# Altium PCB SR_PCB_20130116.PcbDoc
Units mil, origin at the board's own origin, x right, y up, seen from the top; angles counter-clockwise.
Board outline 7185 x 3715 mil, 2 copper layers (Top Layer, Bottom Layer); 142 components, 94 nets, 383 pads, 150 vias.
Unrouted connection lines stored in the file: 1.
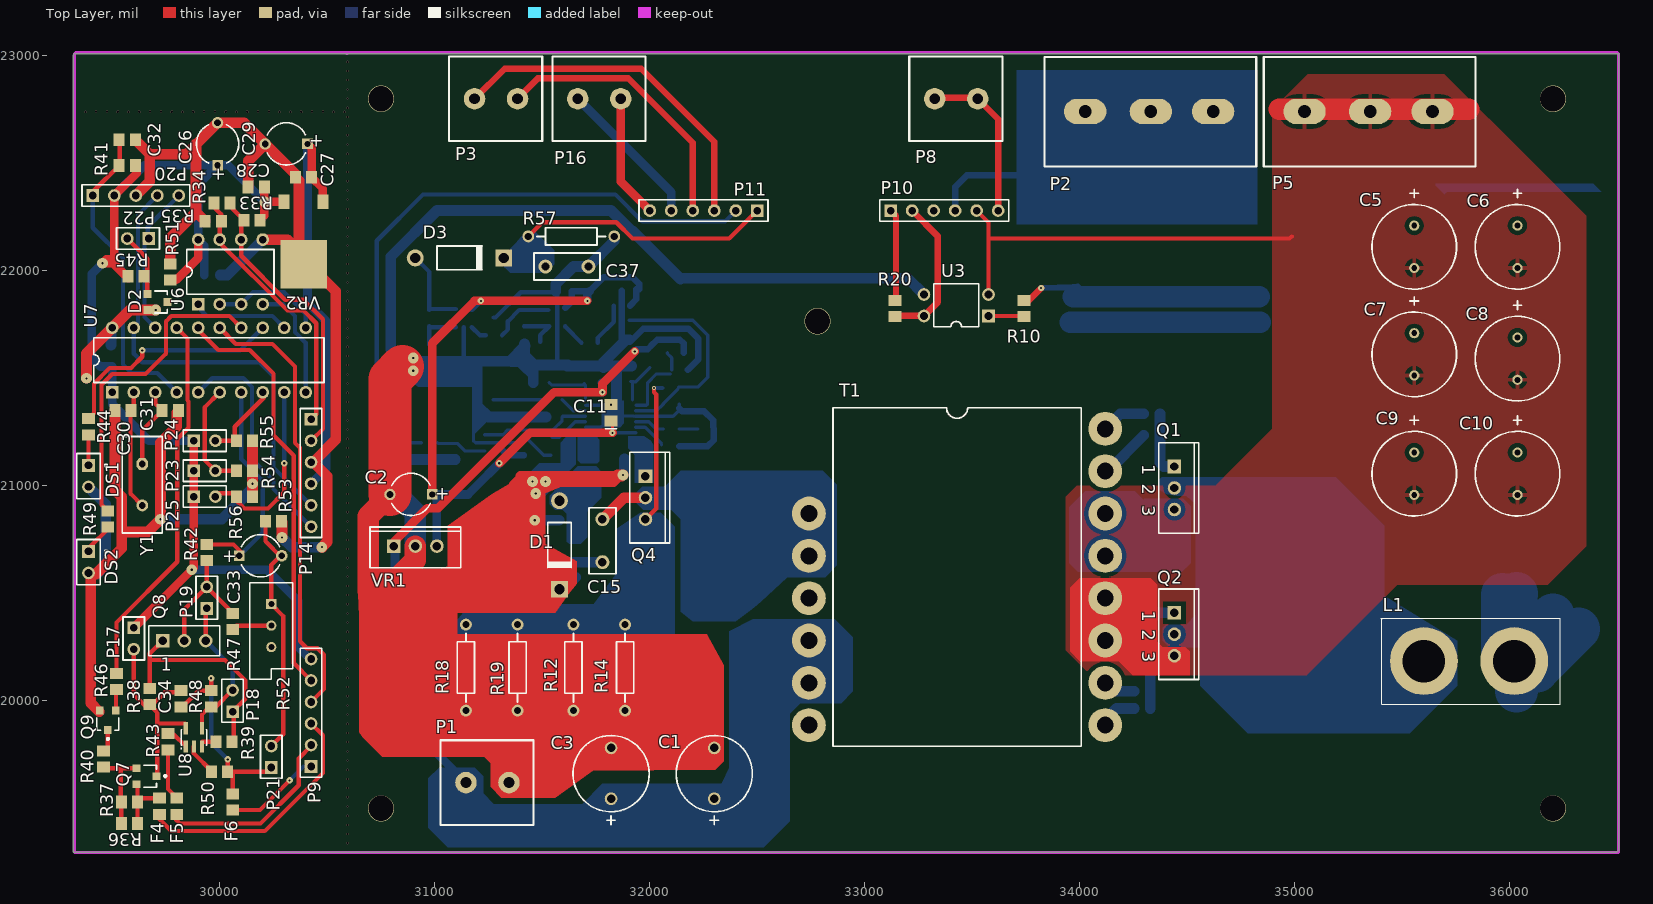
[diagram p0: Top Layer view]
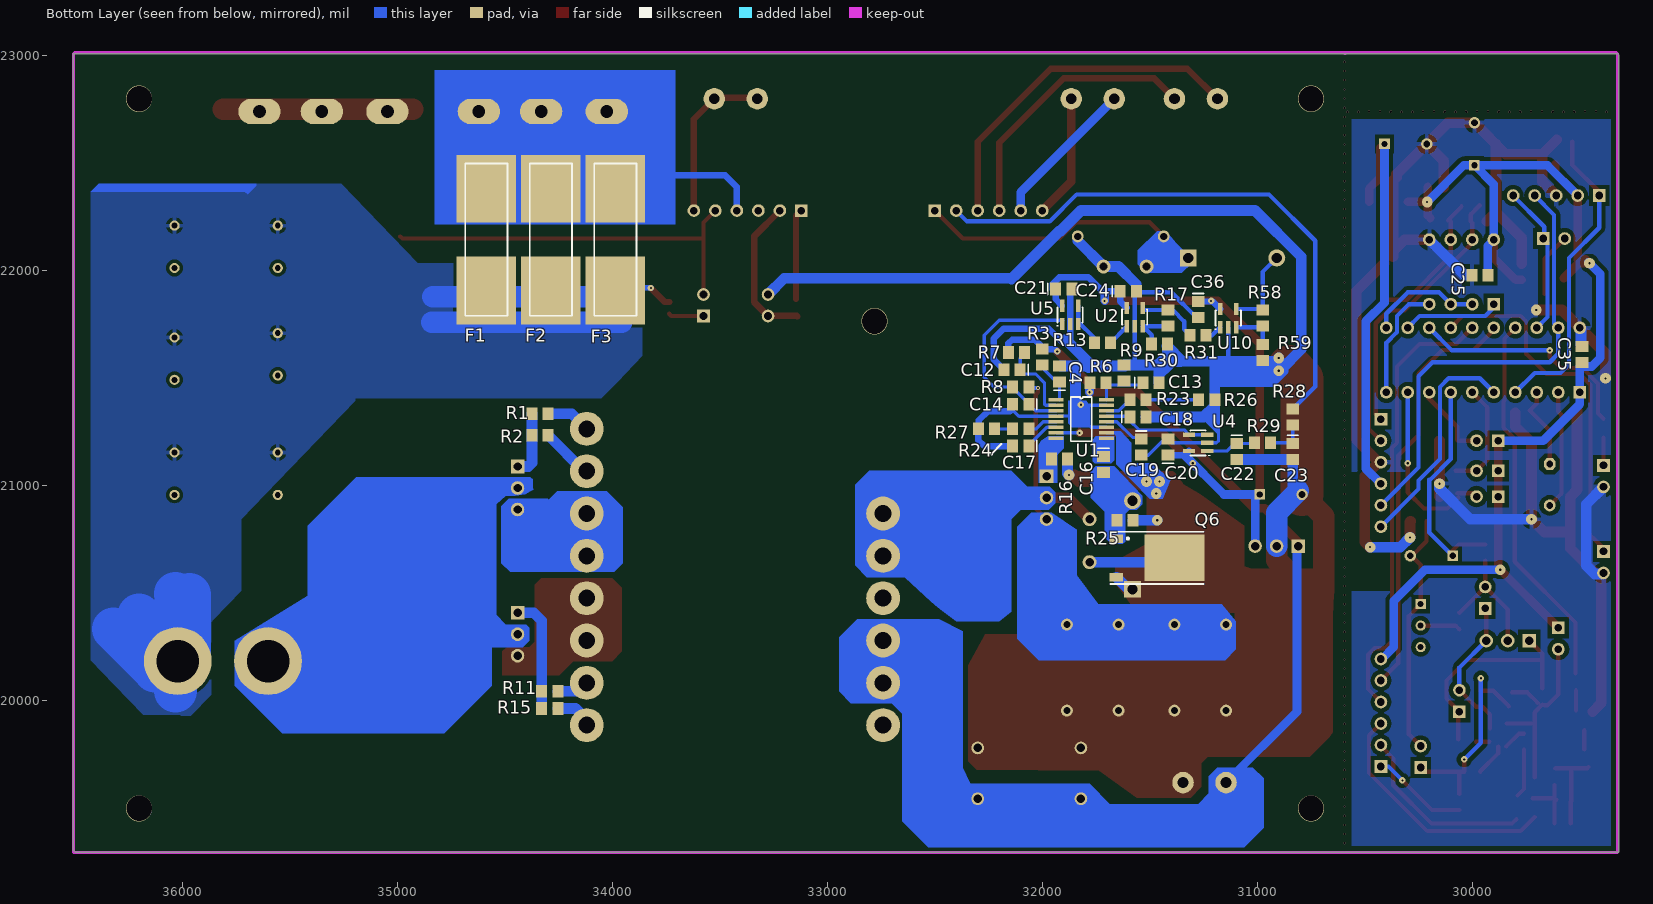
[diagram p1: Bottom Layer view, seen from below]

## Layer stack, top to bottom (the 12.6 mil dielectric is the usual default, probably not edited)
Top Layer: signal copper 1.4
Dielectric: dielectric 12.6, FR-4, Dk 4.8
Bottom Layer: signal copper 1.4

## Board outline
29320,19295 36495,19295 36505,19305 36505,23010 29325,23010 29320,23005 29320,19295

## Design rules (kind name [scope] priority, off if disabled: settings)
Clearance [All] p1: gap=8
ComponentClearance [All] p1: gap=10 collisioncheckmode=3 verticalgap=10
DiffPairsRouting [All] p1: maxlimit=10 minlimit=10 mostfreqgap=10 maxuncoupledlength=500
HoleSize [All] p1: absolutevalues=TRUE maxlimit=300 minlimit=1 maxpercent=80.000 minpercent=20.000
PlaneConnect PlaneConnect_1 [(InNet('CELL1IN'))] p1: planeconnectstyle=Relief reliefexpansion=20 reliefentries=4 reliefconductorwidth=10 reliefairgap=10
PlaneConnect [All] p2: planeconnectstyle=Relief reliefexpansion=20 reliefentries=4 reliefconductorwidth=10 reliefairgap=10
PolygonConnect [All] p1: connectstyle=Relief reliefconductorwidth=20 reliefentries=4 polygonreliefangle="90 Angle"
RoutingVias [All] p1: holewidth=28 width=20 viastyle="Through Hole" minholewidth=10 minwidth=10 maxholewidth=130 maxwidth=150
SolderMaskExpansion [All] p1: expansion=4
TestPointUsage [All] p1: valid=0 allowmultiple=FALSE
Testpoint [All] p1: side=15 testpointundercomponent=TRUE minsize=40 maxsize=100 preferedsize=60 minholesize=0 maxholesize=40 preferedholesize=32 testpointgrid=1 style=1023 order=0-112345678
Width [All] p1: maxlimit=260 minlimit=10 preferedwidth=10 toplayer_prefwidth=15 bottomlayer_prefwidth=15 minimp=50.000000 maximp=50.000000 favimp=50.000000
15 further rules are at their usual default settings.

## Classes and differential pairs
differential pair A: +A_P -A_N

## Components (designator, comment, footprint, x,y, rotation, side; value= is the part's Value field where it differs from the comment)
C1 "Cap Pol1" CAP6 32300,19545 r90 top
C2 "Cap Pol3" CAPPR5-5x5 30890,20960 r180 top
C3 "Cap Pol1" CAP6 31820,19545 r90 top
C4 "Cap Pol3" C0805 31920,21520 r90 bottom
C5 "Cap Pol1" CAP5 35555,22210 r270 top
C6 "Cap Pol1" CAP5 36035,22210 r270 top
C7 "Cap Pol1" CAP5 35555,21710 r270 top
C8 "Cap Pol1" CAP5 36035,21690 r270 top
C9 "Cap Pol1" CAP5 35555,21155 r270 top
C10 "Cap Pol1" CAP5 36035,21155 r270 top
C11 "Cap Pol3" C0805 31820,21340 r90 top
C12 "Cap Pol3" C0805 32140,21540 r0 bottom
C13 "Cap Pol3" C0805 31495,21480 r180 bottom
C14 "Cap Pol3" C0805 32100,21380 r0 bottom
C15 "Cap" VP45-3.2 31780,20745 r90 top
C16 "Cap Pol3" C0805 31715,21100 r270 bottom
C17 "Cap Pol3" C0805 32100,21185 r0 bottom
C18 "Cap Pol3" C0805 31555,21320 r180 bottom
C19 "Cap Pol3" C0805 31540,21180 r270 bottom
C20 "Cap Pol3" C0805 31415,21180 r90 bottom
C21 "Cap Pol3" C0805 31900,21915 r180 bottom
C22 "Cap Pol3" C0805 31095,21160 r270 bottom
C23 "Cap Pol3" C0805 30835,21160 r270 bottom
C24 "Cap Pol3" C0805 31600,21905 r180 bottom
C25 "Cap" 2012[0805] 29965,21980 r180 bottom
C26 "Cap Pol1" CAPPR5-5x5 29990,22590 r90 top
C27 "Cap" 2012[0805] 30390,22435 r180 top
C28 "Cap" 2012[0805] 30170,22390 r180 top
C29 "Cap Pol1" CAPPR5-5x5 30310,22590 r180 top
C30 "Cap" 2012[0805] 29550,21350 r0 top
C31 "Cap" 2012[0805] 29770,21350 r180 top
C32 "Cap" 2012[0805] 29570,22610 r180 top
C33 "Cap" CAPPR5-5x5 30190,20675 r0 top
C34 "Cap" 2012[0805] 29820,20010 r90 top
C35 "Cap" 2012[0805] 29490,21610 r270 bottom
C36 "Cap Pol3" C0805 31275,21820 r270 bottom
C37 "Cap" VP45-3.2 31615,22020 r180 top
D1 "Diode 1N4934" DO-41 31580,20725 r270 top
D2 "D Schottky" SOT23 29710,21855 r270 top
D3 "Diode 1N4934" DO-41 31115,22060 r0 top
DS1 "Lamp" PIN2 29390,21095 r270 top
DS2 "Lamp" PIN2 29390,20695 r270 top
F1 "Fuse 1" fuse30A 34585,22145 r90 bottom
F2 "Fuse 1" fuse30A 34285,22145 r90 bottom
F3 "Fuse 1" fuse30A 33985,22145 r90 bottom
F4 "Fuse 1" 6-0805 29720,19510 r90 top
F5 "Fuse 1" 6-0805 29800,19510 r90 top
F6 "Fuse 1" 6-0805 30060,19530 r90 top
L1 "Inductor Iron" L_circle 35600,20185 r0 top
P1 "Header 2" T2 31460,19620 r180 top
P2 "Header 3" PIN3 34820,22485 r180 top
P3 "Header 2" T2 31500,22800 r180 top
P5 "Header 3" PIN3 35840,22485 r180 top
P8 "Header 2" T2 33640,22800 r180 top
P9 "Header 6" HDR1X6 30425,19695 r90 top
P10 "Header 6" HDR1X6 33120,22280 r0 top
P11 "Header 6" HDR1X6 32500,22280 r180 top
P14 "Header 6" HDR1X6 30425,21310 r270 top
P16 "Header 2" T2 31980,22800 r180 top
P17 "Header 2" HDR1X2 29600,20340 r270 top
P18 "Header 2" HDR1X2 30060,19950 r90 top
P19 "Header 2" HDR1X2 29940,20430 r90 top
P20 "Header 5" HDR1X5 29410,22350 r0 top
P21 "Header 2" HDR1X2 30240,19690 r90 top
P22 "Header 2" HDR1X2 29670,22150 r180 top
P23 "Header 2" HDR1X2 29880,21070 r0 top
P24 "Header 2" HDR1X2 29880,21210 r0 top
P25 "Header 2" HDR1X2 29880,20950 r0 top
Q1 "" TO-220AB 34440,20990 r270 top
Q2 "" TO-220AB 34440,20310 r270 top
Q4 "IRF540N" TO-220AB 31980,20945 r270 top
Q6 "IRFR9120N" TO-252AA 31520,20665 r270 bottom
Q7 "PMOS-2" SOT23 29660,19650 r270 top
Q8 "PNP" 2SB1238 29735,20280 r0 top
Q9 "NPN" SOT23 29480,19910 r180 top
R1 "Res Semi" 2012[0805] 34335,21335 r0 bottom
R2 "Res Semi" 2012[0805] 34335,21235 r0 bottom
R3 "Res Semi" 2012[0805] 32000,21600 r90 bottom
R6 "Res Semi" 2012[0805] 31740,21480 r0 bottom
R7 "Res Semi" 2012[0805] 32120,21620 r0 bottom
R8 "Res Semi" 2012[0805] 32100,21460 r0 bottom
R9 "Res Semi" 2012[0805] 31620,21525 r270 bottom
R10 "Res Semi" 2012[0805] 33740,21825 r90 top
R11 "Res Semi" 2012[0805] 34290,20045 r180 bottom
R12 "Res2" AXIAL-0.4 31645,20155 r90 top
R13 "Res3" 2012[0805] 31720,21665 r180 bottom
R14 "Res2" AXIAL-0.4 31885,20155 r90 top
R15 "Res Semi" 2012[0805] 34290,19965 r0 bottom
R16 "Res Semi" 2012[0805] 31920,21125 r0 bottom
R17 "Res3" 2012[0805] 31415,21780 r90 bottom
R18 "Res2" AXIAL-0.4 31145,20155 r90 top
R19 "Res2" AXIAL-0.4 31385,20155 r90 top
R20 "Res Semi" 2012[0805] 33140,21825 r270 top
R23 "Res Semi" 2012[0805] 31555,21400 r0 bottom
R24 "Res Semi" 2012[0805] 32100,21265 r180 bottom
R25 "Res Semi" 2012[0805] 31615,20840 r0 bottom
R26 "Res Semi" 2012[0805] 31235,21400 r0 bottom
R27 "Res Semi" 2012[0805] 32260,21265 r180 bottom
R28 "Res Semi" 2012[0805] 30835,21320 r90 bottom
R29 "Res Semi" 2012[0805] 30975,21200 r180 bottom
R30 "Res3" 2012[0805] 31455,21660 r0 bottom
R31 "Res3" 2012[0805] 31275,21700 r180 bottom
R33 "Res Semi" 2012[0805] 30150,22235 r180 top
R34 "Res Semi" 2012[0805] 30010,22315 r180 top
R35 "Res Semi" 2012[0805] 29970,22230 r180 top
R36 "Res Semi" 2012[0805] 29580,19430 r0 top
R37 "Res Semi" 2012[0805] 29580,19530 r0 top
R38 "Res Semi" 2012[0805] 29675,20020 r270 top
R39 "Res Semi" 2012[0805] 30020,19810 r180 top
R40 "Res Semi" 2012[0805] 29460,19730 r270 top
R41 "Res Semi" 2012[0805] 29570,22490 r0 top
R42 "Res Semi" 2012[0805] 29940,20690 r270 top
R43 "Res Semi" 2012[0805] 29760,19810 r270 top
R44 "Res Semi" 2012[0805] 29390,21275 r270 top
R45 "Res Semi" 2012[0805] 29610,21975 r180 top
R46 "Res Semi" 2012[0805] 29520,20090 r90 top
R47 "Res Semi" 2012[0805] 30060,20370 r90 top
R48 "Res Semi" 2012[0805] 29960,20010 r270 top
R49 "Res Semi" 2012[0805] 29480,20845 r270 top
R50 "Res Semi" 2012[0805] 30000,19670 r180 top
R51 "Res Semi" 2012[0805] 29770,21995 r90 top
R52 "Res Tap" VR5 30240,20350 r270 top
R53 "Res Semi" 2012[0805] 30250,20835 r180 top
R54 "Res Semi" 2012[0805] 30115,21070 r180 top
R55 "Res Semi" 2012[0805] 30115,21210 r180 top
R56 "Res Semi" 2012[0805] 30115,20950 r180 top
R57 "Res2" AXIAL-0.4 31635,22160 r180 top
R58 "Res3" 2012[0805] 30975,21780 r90 bottom
R59 "Res3" 2012[0805] 30975,21620 r90 bottom
T1 "Trans1" DIP16 32740,21265 r0 top
U1 "LM5025B" TSSOP16 31935,21400 r180 bottom
U2 "LM12CLK" MA05A 31570,21785 r180 bottom
U3 "Optoisolator1" DIP-4 33425,21840 r90 top
U4 "LM12CLK" MA05A 31275,21200 r90 bottom
U5 "LM12CLK" MA05A 31870,21795 r180 bottom
U6 "MAX481ESA" DIP-8 30050,21995 r0 top
U7 "PIC16F687" PDIP300-20 29950,21585 r0 top
U8 "LM12CLK" MA05A 29880,19830 r0 top
U10 "LM12CLK" MA05A 31135,21780 r180 bottom
VR1 "Volt Reg" TO-220-AB 30910,20720 r0 top
VR2 "L78M05ABDT" TO-252 30390,22030 r180 top
Y1 "XTAL" BCY-W2/E4.7 29640,21005 r270 top

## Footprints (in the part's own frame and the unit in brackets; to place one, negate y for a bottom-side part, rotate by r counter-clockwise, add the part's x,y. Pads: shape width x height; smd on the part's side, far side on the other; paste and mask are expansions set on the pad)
2SB1238 [mm]
  rect 1.6x1.6 hole 1: 1(0,0)
  round 1.6 hole 1: 2(2.54,0) 3(5.08,0)
  silkscreen extent -1.65,-1.78 6.73,1.78
6-0805 [mm] "Chip Resistor; Body 2.0 x 1.3 mm (LxW typ)"
  rect 1.3x1.5 smd: 1(-0.95,0) 2(0.95,0)
2012[0805] [mm] "Chip Resistor; Body 2.0 x 1.3 mm (LxW typ)"
  rect 1.3x1.5 smd: 1(-0.95,0) 2(0.95,0)
AXIAL-0.4 [mm] "Resistor; 2 Leads"
  round 1.4 hole 0.85: 1(-5.08,0) 2(5.08,0)
  silkscreen extent -4.06,-1.02 4.06,1.02
BCY-W2/E4.7 [mm] "Quartz Crystal, Thru-Hole; 2 Leads; Body 11.35 x 4.65 x 13.46 mm (LxWxH max)"
  oct 1.4x1.4 hole 0.8: 1(-2.44,0)
  round 1.4 hole 0.8: 2(2.44,0)
  silkscreen extent -5.7,-2.35 5.7,2.35
C0805 [mm] "Chip Capacitor; Body 2.0 x 1.2 mm (LxW typ)"
  rect 1.3x1.5 smd: 1(-0.95,0) 2(0.95,0)
  silkscreen extent -1.9,-0.65 -1.9,0.65
CAP5 [mm]
  round 1.2 hole 0.7: 1(0,0) 2(5,0)
  silkscreen extent -4.32,-5 7.5,5
CAP6 [mm]
  round 1.5 hole 1: 1(0,0) 2(6,0)
  silkscreen extent -3.05,-4.5 7.46,4.5
CAPPR5-5x5 [mm] "Capacitor, Electrolytic, Radial; Body 5 x 5 mm (Dia.xH typ); Pin Spacing 5 mm (typ)"
  rect 1.25x1.25 hole 0.75: 1(-2.5,0)
  round 1.35 hole 0.8: 2(2.5,0)
  silkscreen extent -2.26,-2.5 2.27,2.5
DIP16 [mm]
  round 4 hole 2: 3(0,-10) 4(0,-15) 5(0,-20) 6(0,-25) 7(0,-30) 8(0,-35) 9(35,-35) 10(35,-30) 11(35,-25) 12(35,-20) 13(35,-15) 14(35,-10) 15(35,-5) 16(35,0)
  silkscreen extent 2.83,-37.5 32.17,2.5
DIP-4 [mm] "DIP; 4 Leads; Row Spacing 7.62 mm; Pitch 2.54 mm"
  rect 1.5x1.5 hole 0.9: 1(-1.27,-3.81)
  round 1.5 hole 0.9: 2(1.27,-3.81) 3(1.27,3.81) 4(-1.27,3.81)
  silkscreen extent -2.55,-2.65 2.55,2.65
DIP-8 [mm] "DIP; 8 Leads; Row Spacing 7.62 mm; Pitch 2.54 mm"
  rect 1.5x1.5 hole 0.9: 1(-3.81,-3.81)
  round 1.5 hole 0.9: 2(-1.27,-3.81) 3(1.27,-3.81) 4(3.81,-3.81) 5(3.81,3.81) 6(1.27,3.81) 7(-1.27,3.81) 8(-3.81,3.81)
  silkscreen extent -5.15,-2.65 5.15,2.65
DO-41 [mm] "Diode, Axial; Body 5.2 x 2.7 mm (LxDia. max), Lead Dia. 0.86 mm (max)"
  round 2 hole 1.2: 1(-5.23,0)
  rect 2x2 hole 1.2: 2(5.23,0)
  silkscreen extent -2.65,-1.42 2.74,1.4
fuse30A [mm]
  rect 8x7 smd: 1(-6,0) 2(6,0)
  silkscreen extent -9,-2.5 9,2.5
HDR1X2 [mm] "Connector; Header; 2 Position"
  rect 1.5x1.5 hole 0.9: 1(0,0)
  round 1.5 hole 0.9: 2(2.54,0)
  silkscreen extent -1.27,-1.27 3.81,1.27
HDR1X5 [mm] "Connector; Header; 5 Position"
  rect 1.5x1.5 hole 0.9: 1(0,0)
  round 1.5 hole 0.9: 2(2.54,0) 3(5.08,0) 4(7.62,0) 5(10.16,0)
  silkscreen extent -1.27,-1.27 11.43,1.27
HDR1X6 [mm] "Connector; Header; 6 Position"
  rect 1.5x1.5 hole 0.9: 1(0,0)
  round 1.5 hole 0.9: 2(2.54,0) 3(5.08,0) 4(7.62,0) 5(10.16,0) 6(12.7,0)
  silkscreen extent -1.27,-1.27 13.97,1.27
L_circle [mm]
  round 8 hole 5 mask+0: 1(0,0) 2(10.668,0)
  silkscreen extent -5.08,-5.08 16.13,5.08
MA05A [mm] "SOT-23/SC-74A; 5 Leads; Body 3 x 3 mm, inc. leads (LxW max)"
  rect 0.5x1.45 smd: 1(-0.95,-1.075) 2(0,-1.075) 3(0.95,-1.075) 4(0.95,1.075) 5(-0.95,1.075)
  silkscreen extent -1.55,-1.35 1.5,0.9
PDIP300-20 [mm] "DIP, Plastic; 20 Leads; Row Spacing 7.62 mm; Pitch 2.54 mm"
  rect 1.5x1.5 hole 0.9: 1(-11.43,-3.81)
  round 1.5 hole 0.9: 2(-8.89,-3.81) 3(-6.35,-3.81) 4(-3.81,-3.81) 5(-1.27,-3.81) 6(1.27,-3.81) 7(3.81,-3.81) 8(6.35,-3.81) 9(8.89,-3.81) 10(11.43,-3.81) 11(11.43,3.81) 12(8.89,3.81) 13(6.35,3.81) 14(3.81,3.81) 15(1.27,3.81) 16(-1.27,3.81) 17(-3.81,3.81) 18(-6.35,3.81) 19(-8.89,3.81) 20(-11.43,3.81)
  silkscreen extent -13.6,-2.65 13.6,2.65
PIN2 [mm] "Photosensitive Diode; 2 Leads"
  rect 1.5x1.5 hole 0.9: 1(0,0)
  round 1.5 hole 0.9: 2(2.54,0)
  silkscreen extent -1.4,-1.4 3.94,2.18
PIN3 [mm]
  oval 5x3 hole 1.5 mask+0: 1(5.08,-6.5) 2(12.446,-6.5) 3(20.193,-6.5)
  silkscreen extent 0,-12.95 25.02,0
SOT23 [mm] "SOT-23; 3 Leads; Body 3.1 x 2.5 mm, inc. leads (LxW max), Alternate Lead Configuration"
  rect 0.9x0.95 smd: 1(0,1.175) 2(0.95,-1.175) 3(-0.95,-1.175)
  silkscreen extent -1.3,-0.3 1.3,2.33
T2 [mil]
  round 100 hole 50: 1(115,0) 2(315,0)
  silkscreen extent 0,-197 433,197
TO-220-AB [mm] "TO, Thru-Hole, Vertical, Heatsink Mounted; 3 In-Line Leads; Pitch 2.54 mm"
  rect 1.6x1.6 hole 1: 1(-2.54,0)
  round 1.6 hole 1: 2(0,0) 3(2.54,0)
  silkscreen extent -5.35,-2.55 5.35,2.25
TO-220AB [mm] "TO, Thru-Hole, Vertical, Heatsink Mounted; 3 In-Line Leads; Pitch 2.54 mm"
  rect 1.6x1.6 hole 1: 1(-2.54,0)
  round 1.6 hole 1: 2(0,0) 3(2.54,0)
  silkscreen extent -5.35,-1.85 5.35,2.85
TO-252 [mm]
  rect 1.3x1.7 smd: 1(-2.285,-7.4) 3(2.285,-7.4)
  rect 5.5x5.7 smd: 4(0,0)
TO-252AA [mm] "D-PAK/TO-252-AA; 3 Leads (1 Cropped); Body 10.4 (inc. leads) x 6.7 mm (LxW max)"
  rect 1x1.6 smd: 1(-2.285,-3.425) 3(2.285,-3.425)
  rect 5.5x7.1 smd: 4(0,3.425)
  silkscreen extent -3.09,-4.13 3.09,6.88
TSSOP16 [mm]
  rect 1.78x0.42 smd: 1(0,0) 2(0,-0.65) 3(0,-1.3) 4(0,-1.95) 5(0,-2.6) 6(0,-3.25) 7(0,-3.9) 8(0,-4.55) 9(5.94,-4.55) 10(5.94,-3.9) 11(5.94,-3.25) 12(5.94,-2.6) 13(5.94,-1.95) 14(5.94,-1.3) 15(5.94,-0.65) 16(5.94,0)
  silkscreen extent 1.72,-4.88 4.22,0.33
VP45-3.2 [mm] "Capacitor, Ceramic, Thru-Hole, Dipped Radial; Body 7.8 x 3.2 mm (WxT) Pin Spacing 5.08 mm (typ)"
  round 1.65 hole 1: 1(-2.54,0) 2(2.54,0)
  silkscreen extent -3.9,-1.6 3.9,1.6
VR5 [mm] "Potentiometer; 3 Leads"
  rect 1.2x1.2 hole 0.7: 1(-2.54,0)
  round 1.2 hole 0.7: 2(0,0) 3(2.54,0)
  silkscreen extent -5.08,-2.54 6.35,2.54

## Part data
C1 C3 C5 C6 C7 C8 C9 C10 C26 C29: "Polarized Capacitor (Radial)"
C2 C4 C11 C12 C13 C14 C16 C17 C18 C19 C20 C21 C22 C23 C24 C36: "Polarized Capacitor (Surface Mount)"
C15 C25 C27 C28 C30 C31 C32 C33 C34 C35 C37: "Capacitor"
D1 D3: "1 Amp Fast Recovery Rectifier"
D2: "Schottky Diode"
DS1 DS2: "Incandescent Bulb"
F1 F2 F3 F4 F5 F6: "Fuse"
L1: "Magnetic-Core Inductor"
P1 P3 P8 P16 P17 P18 P19 P21 P22 P23 P24 P25: "Header, 2-Pin"
P2 P5 P11 P14: library part "Header 2", "Header, 2-Pin"
P9 P10: library part "Header 7", "Header, 7-Pin"
P20: "Header, 5-Pin"
Q1 Q2: library part IRFH6200
Q4 Q6: "HEXFET Power MOSFET"
Q7: "P-Channel Power MOSFET"
Q8: "PNP Bipolar Transistor"
Q9: "NPN Bipolar Transistor"
R1 R2 R3 R6 R7 R8 R9 R10 R11 R15 R16 R20 R23 R24 R25 R26 R27 R28 R29 R33 R34 R35 R36 R37 R38 R39 R40 R41 R42 R43 R44 R45 R46 R47 R48 R49 R50 R51 R53 R54 R55 R56: "Semiconductor Resistor"
R12 R13 R14 R17 R18 R19 R30 R57 R58 R59: "Resistor"
R31: library part "Res Semi", "Semiconductor Resistor"
R52: "Tapped Resistor"
U2 U4 U5 U8 U10: "80W Operational Amplifier"
U3: "4-Pin Phototransistor Optocoupler"
U6: "Low-Power, Slew-Rate-Limited RS-485/RS-422 Transceiver"
VR1: "Voltage Regulator"
VR2: "Precision 500mA Regulator"
Y1: "Crystal Oscillator"

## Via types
v1: diameter 10, hole 10, Top Layer to Bottom Layer, 115 vias
v2: diameter 50, hole 10, Top Layer to Bottom Layer, 16 vias
v3: diameter 30, hole 10, Top Layer to Bottom Layer, 13 vias
v4: diameter 122.05, hole 118.11, Top Layer to Bottom Layer, 5 vias
v5: diameter 20, hole 10, Top Layer to Bottom Layer, 1 vias

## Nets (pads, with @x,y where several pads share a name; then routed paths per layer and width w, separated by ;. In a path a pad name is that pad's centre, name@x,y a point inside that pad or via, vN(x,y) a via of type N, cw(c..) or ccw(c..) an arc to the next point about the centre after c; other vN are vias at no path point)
+5V: C25.2 C26.1 C28.1 C35.2 P9.6 P17.1 P20.2 P23.1 P24.1 P25.1 R33.1 R41.2 R45.2 R51.1 U6.8 U7.1 VR2.3 | length 5620.9
  Top Layer w40: R45.2@29575,21965 29505,22035 v2(29455,22035) 29472.6,22052.6 29510,22052.6 P20.2 29615,22455 R41.2@29615,22495 ; P17.1 29880,20620 P24.1 ; R51.1 29797.6,21957.6 29900,22060 U6.8 ; R33.1@30195,22245 30207.4,22257.4 C28.1 ; v2@30207.4,22320 30208.74,22321.34 VR2.3
  Bottom Layer w40: v2@29460,22040 29405,21985 29405,21595 29445,21555 29500,21555 29500,21380 29670,21210 P24.1 ; P20.2 29650,22490 C26.1@29980,22490 ; v2(29870,20610) 30220,20610 30365,20465 30365,20250 30420,20195 P9.6 ; C25.2 29927.6,22117.4 U6.8 29900,22401.57 C26.1 30038.43,22491.57 v2(30210,22320)
+5VIN: P10.1 R20.1 | length 420.4
  Top Layer w30: P10.1 33145,22255 R20.1@33145,21870
+12V: C2.1 C11.1 C20.1 C21.1 C24.1 C36.1 U1.7 U2.5 U4.5 U5.5 U10.5 VR1.3 | length 3751.7
  Top Layer w15: v3(31826.46,21246.46) C11.1@31826.46,21296.14
  Top Layer w40: C2.1 30988.43,21663.43 31185,21860 v3(31710,21860) ; v3(31300,21105) 31441.46,21246.46 v3(31826.46,21246.46)
  Bottom Layer w15: v3(31826.46,21246.46) U1.7
  Bottom Layer w30: U10.5 31207.48,21857.4 C36.1 ; U4.5 31337.32,21142.6 C20.1 ; U2.5 31637.4,21857.32 C24.1 31720,21905 31785,21970 31920,21970 31950,21940 C21.1@31950,21915 ; U5.5@31908,21837.92 31937.4,21867.32 C21.1
  Bottom Layer w40: VR1.3 31010,20938.43 C2.1 31154.72,20960 31337.32,21142.6 ; v3(31710,21860) 31710,21895 31720,21905
  other v3: 31215,21860
+24V: C1.1 C3.1 P1.2 R3.2 R6.2 R7.2 T1.6 T1.7 VR1.1 | length 3093.6
  Top Layer w40: VR1.1 30810,20740 30965.51,20895.51 31015.51,20895.51 31555,21435 v3(31780,21435) 31780,21475 v3(31930,21625)
  Bottom Layer w30: v3(31930,21625) 31940,21635 R3.2@31990,21635 ; R3.2@32005,21650 32035,21680 32140,21680 32157.4,21662.6 R7.2
  Bottom Layer w40: VR1.1 30815,20715 30815,19950 P1.2 ; R6.2 31780,21477.4 v3(31780,21435)
A_N: P14.2 R33.2 R34.1 U6.6 | length 1340.9
  Top Layer w20: R34.1@30050,22300 30050,22297.6 R33.2 ; R33.2@30100,22230 30100,22070 30305,21865 30390,21865 30480,21775 30480,21265 P14.2
A_P: P14.1 R34.2 R35.1 U6.7 | length 1259.3
  Top Layer w20: R34.2@29965,22305 30007.4,22262.6 R35.1 30000,22222.6 U6.7 29995,22140 29995,22135 30315,21815 30390,21815 30448.62,21756.38 30448.62,21333.62 P14.1
AN7: C33.1 R42.1 U7.7 | length 1026.3
  Top Layer w20: R42.1 30064.17,20727.4 C33.1@30101.57,20690
  Bottom Layer w20: C33.1 30200,20783.43 30200,21030 30195,21030 30100,21125 U7.7
CELL1: F4.1 P9.3 | length 1161.5
  Top Layer w20: F4.1@29710,19460 29775,19395 30210,19395 30480,19665 30480,19840 P9.3
CELL1IN: F1.2 F2.2 F3.2 P2.1 P2.2 P2.3 P10.4 | length 457.8
  Bottom Layer w30: P10.4 33420,22390 33475,22445 33745,22445
CELL2: F5.1 P9.2 | length 865.6
  Top Layer w20: F5.1@29795,19450 29815,19430 30190,19430 30367.53,19607.53 30367.53,19732.53 30425,19790 P9.2
CELL2IN: C5.2 C6.2 C7.2 C8.2 C9.2 C10.2 P5.1 P5.2 P5.3 P10.5 Q2.3 T1.11 T1.12 U3.2 | length 2708.8
  Top Layer w20: P10.5 33575,22225 U3.2 ; 33575,22150 34975,22150 34985,22160
  Top Layer w100: 34927.18,22750.91 35809.09,22750.91
CELL3: F6.1 P9.1 | length 448.8
  Top Layer w20: F6.1 30187.6,19492.6 v3(30325,19630)
  Bottom Layer w20: v3(30325,19630) 30390,19695 P9.1
CELL3IN: P8.1 P8.2 P10.6 | length 771.4
  Top Layer w30: P8.2@33315,22805 33520,22805 33620,22705 P10.6
COMP: C18.1 U1.13 U4.3 U4.4 | length 509.8
  Bottom Layer w15: U4.3 U4.4 31339.92,21260 31550,21260 31592.4,21302.4 C18.1 ; C18.1@31595.63,21323.23 U1.13
CS1: C14.1 R8.2 U1.3 U5.1 | length 981.1
  Bottom Layer w15: U5.1@31905,21770 32200,21770 32270,21700 32270,21505 32225,21460 R8.2@32135,21460 ; U1.3 32031.42,21348.82 C14.1 32062.6,21382.6 R8.2@32130,21450
CS1OUT: Q4.3 R8.1 R12.2 R14.2 R18.2 R19.2 | length 672.5
  Top Layer w20: Q4.3 32030,20895 32030,21425 32020,21435 v5(32020,21455)
  Bottom Layer w20: v5(32020,21455) R8.1@32057.6,21455
NetC4_1: C4.1 R3.1 U1.1 | length 205.5
  Bottom Layer w15: C4.1@31910,21485 C4.1@31925,21485 ; U1.1@31920,21400 C4.1 31932.6,21482.6 R3.1@32000,21550
NetC5_1: C5.1 C6.1 C7.1 C8.1 C9.1 C10.1 F1.1 F2.1 F3.1 L1.2 R10.2 | length 3214.4
  Top Layer w30: R10.2@33735,21855 33755,21855 v3(33820,21920)
  Bottom Layer w30: v3(33820,21920) 33968.69,21924.37 33984.53,21924.84 F3.1@33990,21925
  Bottom Layer w100: F3.1@33955,21760 34840,21760 ; F3.1@33970,21880 34835,21880
  Bottom Layer w200: 35965,20495 35965,20190 L1.2@35990,20165 ; L1.2@36025,20140 36125,20140 36320,20335 ; L1.2@36030,20045 L1.2@36030,20195 ; L1.2@36030,20180 L1.2@36040,20180 ; 36030,20495 36030,20500 ; L1.2@36040,20165 36040,20240 36200,20400
NetC12_1: C12.1 R7.1 U1.2 | length 367.5
  Bottom Layer w15: U1.2@31936.82,21374.41 31984.41,21374.41 31990,21380 31990,21480 32030,21520 C12.1@32095,21520 ; R7.1 32080,21617.4 32102.6,21594.8 C12.1
NetC13_1: C13.1 R6.1 R9.2 U1.16 | length 250.9
  Bottom Layer w15: C13.1 31543.54,21468.86 R6.1@31701.14,21468.86 ; R6.1@31695,21475 R6.1@31701.14,21468.86 ; U1.16 R6.1@31701.14,21468.86
NetC15_1: C15.1 Q6.4 | length 372.4
  Bottom Layer w50: Q6.4@31420,20675 31450,20645 C15.1
NetC15_2: C15.2 Q4.2 T1.3 T1.4 | length 241.4
  Top Layer w50: C15.2 31880,20945 Q4.2
NetC16_2: C16.2 D1.1 Q6.1 R25.2
NetC17_1: C17.1 U1.6 | length 156.9
  Bottom Layer w15: U1.6 31977.95,21272.05 32055,21195 C17.1@32055,21190
NetC19_1: C19.1 U1.12 | length 186.2
  Bottom Layer w15: C19.1@31545,21225 31580,21225 31652.64,21297.64 U1.12
NetC22_1: C22.1 R29.1 U4.1 | length 235.8
  Bottom Layer w15: R29.1 31015,21197.4 31105.22,21197.4 31140.03,21162.6 U4.1
NetC23_1: C23.1 R28.1 R29.2 | length 188.9
  Bottom Layer w15: R28.1 C23.1 30837.6,21200 R29.2
NetC27_1: C27.1 C29.1 P14.4 VR2.1 | length 1943.1
  Top Layer w40: C29.1 30427.4,22571.02 C27.1 30479.96,22382.44 VR2.1
  Bottom Layer w40: C29.1 30408.43,21851.57 30495,21765 30495,21080 P14.4
NetC32_2: C32.2 P20.1 R41.1 U7.4 | length 1431.2
  Top Layer w20: P20.1@29410,22367.4 29535,22492.4 C32.2@29535,22600
  Bottom Layer w20: P20.1 29410,22200 29550,22060 29550,21565 29590,21525 29710,21525 U7.4
NetC33_2: C33.2 P21.2 R52.1 R53.2 | length 1171.8
  Top Layer w20: R53.2 30212.6,20742.4 C33.2@30290,20665 ; P21.2 30295,19845 30295,20395 R52.1 30240,20631.57 C33.2@30298.43,20690
NetC34_1: C34.1 F6.2 P21.1 R48.1 R50.1 | length 1000.5
  Top Layer w20: C34.1@29830,19975 29902.4,20047.4 R48.1 ; R48.1@29960,20045 v3(29960,20105) ; v3(30037.4,19727.6) R50.1 30220,19670 P21.1 ; F6.2 R50.1@30060,19670
  Bottom Layer w20: v3(29960,20105) 29960,19805 v3(30037.4,19727.6)
NetC34_2: C34.2 P17.2 Q7.1 R38.2 U8.5 | length 918.5
  Top Layer w20: P17.2 29600,20030 29650,19980 R38.2@29665,19980 ; R38.2 29710,19947.6 Q7.1@29710,19645 ; R38.2@29695,19990 29745,20040 C34.2@29815,20040 ; 29710,19895 U8.5@29840,19895
NetC37_2: C37.2 D3.2 P11.1 R57.2 | length 1506.1
  Top Layer w20: R57.2 31500.73,22225.73 31844.27,22225.73 31920,22150 32370,22150 P11.1
  Bottom Layer w20: D3.2 31420.91,22160 R57.2 31515,22080 C37.2
NetD2_2: D2.3 P22.2 R45.1 | length 296.4
  Top Layer w20: P22.2 29663.74,22056.26 D2.3
NetD3_1: D3.1 R58.2 U10.4 | length 395.7
  Bottom Layer w20: D3.1 30975,21994.09 R58.2 ; R58.2@30975,21830 30982.68,21822.32 U10.4
NetDS1_1: DS1.1 R44.2 | length 130
  Top Layer w20: DS1.1 R44.2@29390,21225
NetDS2_1: DS2.1 R49.2 | length 143.1
  Top Layer w20: DS2.1@29400,20690 29400,20720 R49.2@29480,20800
NetF4_2: F4.2 Q7.2 R36.2 R37.2 | length 292
  Top Layer w20: R37.2@29610,19540 29617.4,19547.4 F4.2 ; R36.2 Q7.2@29617.4,19608.94
NetF5_2: F5.2 R43.2 | length 225
  Top Layer w20: R43.2 29760,19590 F5.2@29790,19560
NetL1_1: L1.1 Q1.2 Q2.2
NetP3_1: P3.2 P11.3 | length 1633.8
  Top Layer w30: P3.2 31325,22940 31960,22940 32300,22600 P11.3
NetP3_2: P3.1 P11.4 | length 1293.6
  Top Layer w30: P3.1 31480,22895 31900,22895 32200,22595 P11.4
NetP11_5: P11.5 P16.2 | length 700.2
  Bottom Layer w40: P16.2 32100,22365 P11.5
NetP11_6: P11.6 P16.1 | length 585.9
  Top Layer w40: P16.1@31865,22810 31865,22415 P11.6
NetP18_1: P18.1 Q8.1 R38.1 R39.1 | length 1033.7
  Top Layer w20: R38.1 29675,20220 Q8.1 ; 29675,20190 30025,20190 30120,20095 30120,20010 P18.1 30065,19945 R39.1@30065,19820
NetP18_2: P18.2 P19.1 Q8.3 R48.2 U8.4 | length 670
  Top Layer w20: U8.4 29917.4,19937.4 R48.2@29950,19970 ; Q8.3 P19.1@29935,20425 ; R48.2 29982.6,19972.6 P18.2
  Bottom Layer w20: Q8.3 30060,20155 P18.2
NetP19_2: P19.2 Q8.2 R42.2 R47.2 | length 585.8
  Top Layer w20: Q8.2 29835,20425 P19.2 ; R42.2 P19.2 ; R47.2@30060,20410 P19.2
NetQ1_1: Q1.1 R1.2 R2.2 | length 302.3
  Bottom Layer w50: R1.2 34372.4,21107.6 34390,21090 Q1.1
NetQ1_3: Q1.3 T1.13 T1.14
NetQ2_1: Q2.1 R11.1 R15.2 | length 542.6
  Bottom Layer w50: R15.2 34327.4,20372.4 34365,20410 Q2.1 ; Q2.1@34425,20410 Q2.1@34430,20415
NetQ7_1: Q7.3 R36.1 R37.1 R40.2 | length 486.7
  Top Layer w20: R40.2 29465.2,19687.4 Q7.3 29542.4,19687.4 29540,19685 29540,19532.6 R37.1 R36.1
NetQ9_1: Q9.1 R40.1 | length 88.7
  Top Layer w20: R40.1@29480,19775 Q9.1
NetQ9_2: Q9.3 R46.1 | length 93.7
  Top Layer w20: Q9.3 R46.1@29517.4,20050
NetR1_1: R1.1 T1.16 | length 208.6
  Bottom Layer w50: T1.16 34187.95,21335 R1.1
NetR2_1: R2.1 T1.15 | length 248.8
  Bottom Layer w50: T1.15 34130.75,21068.15 R2.1
NetR10_1: R10.1 U3.1 | length 164.1
  Top Layer w20: U3.1 33725,21790 R10.1@33735,21800
NetR11_2: R11.2 T1.10 | length 150.8
  Bottom Layer w50: T1.10 34156.85,20045 R11.2
NetR13_1: R13.1 U5.3 U5.4 | length 203.5
  Bottom Layer w20: R13.1 31757.4,21687.4 31832.6,21762.6 U5.4
NetR13_2: R13.2 U2.1 | length 108.8
  Bottom Layer w20: U2.1 31607.4,21740.2 R13.2
NetR15_1: R15.1 T1.9 | length 194.5
  Bottom Layer w30: T1.9@34100,19900 T1.9@34120,19900
  Bottom Layer w50: T1.9@34105,19900 34170,19965 R15.1
NetR17_1: R17.1 R30.2 U2.3 | length 207.7
  Bottom Layer w20: R17.1 31532.52,21742.6 31490,21700.08 R30.2@31490,21670
NetR17_2: R17.2 R31.1 U2.4 | length 285.5
  Bottom Layer w20: R31.1 31340,21727.6 31340,21765 31392.4,21817.4 R17.2 U2.4@31527.4,21817.4
NetR23_1: R23.1 R26.2 | length 245.2
  Bottom Layer w15: R26.2 R23.1
NetR23_2: R23.2 U1.14 | length 129.9
  Bottom Layer w15: R23.2 31643.58,21348.82 U1.14
NetR24_1: R24.1 R27.2 | length 85.2
  Bottom Layer w15: R24.1 R27.2
NetR24_2: R24.2 U1.5 | length 141.1
  Bottom Layer w15: U1.5 31995,21297.64 32027.64,21265 R24.2
NetR31_2: R31.2 U10.1 | length 80.8
  Bottom Layer w20: U10.1 31210.08,21700 R31.2
NetR39_2: R39.2 U8.3 | length 62.6
  Top Layer w20: U8.3@29920,19810 R39.2
NetR43_1: R43.1 U8.1 | length 107.3
  Top Layer w20: R43.1 29782.87,19847.4 U8.1
NetR47_1: R47.1 R52.2 | length 187.2
  Top Layer w20: R47.1 30077.4,20350 R52.2
NetR50_2: R50.2 U8.2 | length 151.9
  Top Layer w20: U8.2 29880,19755 29962.6,19672.4 R50.2
NetR58_1: R58.1 R59.2 U10.3 | length 209.8
  Bottom Layer w20: R59.2 R58.1 30979.92,21737.68 U10.3
NetU6_1: U6.1 U7.12 | length 446.4
  Bottom Layer w20: U6.1@29895,21835 29940,21790 30245,21790 U7.12
NetU6_2: U6.2 U6.3 U7.11 | length 539.2
  Bottom Layer w20: U6.2 U6.3 30155,21900 30235,21900 30235.2,21899.8 ; 30225.2,21899.8 30300.2,21899.8 30400,21800 U7.11
NetU6_4: U6.4 U7.10 | length 548.5
  Bottom Layer w20: U6.4 30295,21845 30350,21790 30350,21715 30400,21665 U7.10
OUTA: Q4.1 R16.2 U1.8
OUTB: C16.1 U1.9
PCLK: P14.5 P20.4 U7.19 | length 2146.5
  Bottom Layer w20: P20.4 29620,22260 29620,21755 U7.19 29600,21615 29640,21575 30185,21575 30250,21510 30250,21085 P14.5
PDAT: P20.5 P22.1 U7.18 | length 716.1
  Bottom Layer w20: P22.1@29665,22145 29665,22205 P20.5@29815,22355 ; P22.1 29650,22130 29650,21785 U7.18
PGND: C1.2 C2.2 C3.2 C4.2 C11.2 C12.2 C13.2 C14.2 C17.2 C18.2 C19.2 C20.2 C21.2 C22.2 C23.2 C24.2 C25.1 C26.2 C27.2 C28.2 C29.2 C30.1 C31.1 C32.1 C35.1 C36.2 C37.1 D1.2 D2.2 DS1.2 DS2.2 P1.1 P14.3 P20.3 Q6.3 Q9.2 R9.1 R12.1 R14.1 R16.1 R18.1 R19.1 R25.1 R26.1 R27.1 R30.1 R35.2 R51.2 R53.1 R54.1 R55.1 R56.1 R57.1 R59.1 U1.4 U1.10 U1.11 U1.15 U2.2 U3.3 U4.2 U5.2 U6.5 U7.20 U10.2 VR1.2 VR2.4 | length 21781.4
  Top Layer w50: v2(29380,21500) 29380,21615 29582.6,21817.6 v2(29702.6,21817.6) ; Q9.2@29440,19950 29400,19990 29400,20590 29425,20590 29545,20710 29545,20948.16 29512.6,20980.56 C30.1 ; 29555,20785 29665,20785 v2(29725,20845) 29725,21200.81 29800,21275.81 C31.1@29800,21340 ; C32.1 29675,22542.4 ; P20.3 29675,22415 29675,22542.4 ; R51.2 29770,22152.6 29890,22272.6 ; 29890,22590 29890,22272.6 ; R35.2 29890,22272.6 ; C28.2 30132.6,22511.02 C29.2 ; R56.1 R55.1 ; U6.5 30315,22145 VR2.4@30370,22090 ; R53.1 30290,20832.4 v2(30290,20760) ; VR2.4@30368.81,22066.19 30368.81,22418.79 C27.2 30352.6,22448.98 30113.15,22688.43 C26.2 29843.98,22542.4 29675,22542.4 ; VR2.4@30410,22035 30540,21905 30540,21215 P14.3@30435,21110 ; P14.3 P14.3@30435,21110 ; v2@30476.24,20713.87 30500,20740 30500,21045 P14.3@30435,21110 ; C2.2 C2.2@30808.29,20943.29 ; 31370,21005 31400,21035 ; 31400,21045 31870,21045 v2(31875,21050) v2@31850,21050 ; 31415,21020 31830,21020 31850,21040
  Top Layer w100: 30690,20510 30690,20858.43 C2.2 ; 30830,20575 30910,20655 VR1.2
  Top Layer w200: C2.2 30791.57,21496.57 30850,21555
  Bottom Layer w15: R26.1@31180,21390 31180,21210 31190,21200 31397.6,21200 C20.2 31432.6,21217.4 31507.4,21142.6 C19.2 ; D1.2@31577.6,20530 31577.6,20521.5 D1.2 ; 31641.46,21246.46 U1.10 ; Q6.3@31647.4,20567.6 Q6.3 ; 31655,21245.88 31655,21246.46 ; U1.11 31772.05,21272.05 31785,21285 ; U1.15 31780.59,21374.41 ; 31855,21325 31925,21325 U1.4@31926.77,21323.23 ; U1.4 32108.23,21323.23 32137.4,21352.4 C14.2
  Bottom Layer w20: U10.2 31135,21585 31140,21580 ; C36.2 31282.6,21782.6 31400,21900 31552.6,21900 C24.2@31562.6,21910 ; C24.2@31562.6,21915 31570,21907.6 31570,21567.4 31565,21562.4 ; C4.2@31905,21557.4 C4.2@31910,21562.4
  Bottom Layer w30: 31870,21655 C21.2@31870,21907.6 ; 31905,21680 31919.01,21680 31969.01,21730 32180,21730 32225,21685 32225,21587.6 C12.2 ; C17.2 32270,21185 32297.4,21212.4 R27.1 ; C14.2@32137.4,21360 32149.8,21347.6 32252.4,21347.6 32295,21305 R27.1@32295,21275
  Bottom Layer w50: DS1.2 29470,20915 29470,20630 29430,20590 DS2.2@29400,20590 ; C35.1@29495,21655 29495,21730 U7.20 ; v2(29725,20845) 30010,20845 30152.4,20987.4 v2(30152.4,21010) ; C25.1 30035,21980 U6.5 ; v2(30290,20760) 30335,20715 v2(30475,20715) ; C2.2@30808.29,20976.71 30835,21003.43 C23.2 C22.2 ; 30880,21570 30880,21535 30930,21485 31197.6,21485 ; v2@30890,21540 30795,21635 30795,22065 31010,22280 31820,22280 31917.5,22182.5 ; v2(30900,21595) 30915,21580 31350,21580 R30.1@31420,21650 ; v2@30901.21,21513.79 30908.54,21531.46 30908.84,21532.2 30910,21535 31197.6,21535 ; 31200,21580 31197.6,21577.6 31197.6,21372.4 31250,21320 C18.2 ; R30.1 31417.6,21607.4 31462.6,21562.4 R9.1 ; C13.2 31457.6,21567.4 ; v2(31465,20840) R25.1 ; C24.2 31562.6,21937.6 31645,22020 C37.1 31835,22140 R57.1 ; D1.2 31598.9,20519.09 Q6.3 ; R9.1@31610,21562.4 R9.1@31615,21557.4 ; R9.1@31620,21557.4 C4.2@31915,21557.4 ; 31785,21550 31785,21575 31890,21680 31905,21680 ; 31845,21377.4 31845,21552.4 31850,21557.4 ; v2(31875,21050) 31882.6,21057.6 R16.1 ; 31920,22185 32142.5,21962.5 ; 32145,21965 33200,21965 U3.3
  Bottom Layer w100: C2.2@30808.29,20976.71 30910,20875 VR1.2
  other v2: 31470,20965 31455,21020 31515,21020 30900,21535
  other v3: 31820,21377.4
RA4: C31.2 U7.3 Y1.1 | length 385.8
  Top Layer w20: Y1.1 29640,21257.4 C31.2 29700,21382.6 U7.3
RA5: C30.2 U7.2 Y1.2 | length 555.1
  Top Layer w20: U7.2 29600,21345 29585,21330 29585,20963.94 Y1.2
RB4: R44.1 U7.13 | length 1083.2
  Top Layer w20: R44.1 29415,21337.4 29415,21475 29488,21548 29588,21548 29640,21600 v3(29640,21630)
  Bottom Layer w20: v3(29640,21630) 30095,21630 U7.13
RC0: P9.5 U7.16 | length 1943.6
  Top Layer w20: U7.16 29900,21725 29993,21632 30140,21632 30250,21522 30250,21235 30345,21140 30345,20175 P9.5
RC0IN: P10.2 R20.2 U3.4 | length 695.6
  Top Layer w30: R20.2 33142.4,21790 U3.4 ; P10.2 33340,22160 33340,21855 U3.4@33280,21795
RC1: P9.4 U7.15 | length 2094.6
  Top Layer w20: U7.15 30075,21660 30245,21660 30350,21555 30350,21200 30373,21177 30373,20277 30405,20245 30455,20245 30485,20215 30485,20055 P9.4
RC1IN: P10.3
RC2: R49.1 U7.14 | length 1493.2
  Top Layer w20: R49.1 29450,20912.4 29450,21470 29500,21520 29655,21520 29750,21615 29750,21765 29775,21790 30045,21790 U7.14
RC4: P23.2 R54.2 U7.6 | length 512.3
  Top Layer w20: U7.6 29930,21365 29930,21120 P23.2 R54.2
RC5: P14.6 U7.5 | length 1057.4
  Bottom Layer w20: U7.5 29965,21500 30110,21500 30150,21460 30150,21125 30250,21025 30250,20985 P14.6
RC5_IN: P11.2 R28.2 | length 2664.7
  Bottom Layer w20: R28.2 30730,21462.4 30730,22140 30945,22355 31840,22355 31965,22230 32350,22230 P11.2@32405,22285
RC6: P24.2 R55.2 U7.8 | length 373
  Top Layer w20: P24.2 30065,21210 30070,21215 30070,21275 30205,21410 U7.8@30205,21440
RC7: P25.2 R56.2 U7.9 | length 848
  Top Layer w20: P25.2 29995,20965 R56.2@30070,20965 ; R56.2@30065,20945 30115,20895 30225,20895 30300,20970 v3(30300,21105)
  Bottom Layer w20: v3(30300,21105) U7.9
SC: R46.2 U7.17 | length 1769.1
  Top Layer w20: R46.2 29520,20365 29802.48,20647.48 29802.48,21217.48 29855,21270 29855,21392.53 29850,21397.53 29850,21685 U7.17
pads on no net: D2.1 R52.3 T1.5 T1.8
copper on no net:
  other v1: 30595,19295 30595,19295 30595,19337.76 30595,19380.52 30595,19423.28 30595,19466.03 30595,19508.79 30595,19551.55 30595,19594.31 30595,19637.07 30595,19679.83 30595,19722.59 30595,19765.34 30595,19808.1 30595,19850.86 30595,19893.62 30595,19936.38 30595,19979.14 30595,20021.9 30595,20064.65 30595,20107.41 30595,20150.17 30595,20192.93 30595,20235.69 30595,20278.45 30595,20321.21 30595,20363.97 30595,20406.72 30595,20449.48 30595,20492.24 30595,20535 30595,20577.76 30595,20620.52 30595,20663.28 30595,20706.03 30595,20748.79 30595,20791.55 30595,20834.31 30595,20877.07 30595,20919.83 30595,20962.59 30595,21005.34 30595,21048.1 30595,21090.86 30595,21133.62 30595,21176.38 30595,21219.14 30595,21261.9 30595,21304.65 30595,21347.41 30595,21390.17 30595,21432.93 30595,21475.69 30595,21518.45 30595,21561.21 30595,21603.96 30595,21646.72 30595,21689.48 30595,21732.24 30595,21775 30595,21817.76 30595,21860.52 30595,21903.27 30595,21946.03 30595,21988.79 30595,22031.55 30595,22074.31 30595,22117.07 30595,22159.83 30595,22202.58 30595,22245.34 30595,22288.1 30595,22330.86 30595,22373.62 30595,22416.38 30595,22459.14 30595,22501.9 30595,22544.65 30595,22587.41 30595,22630.17 30595,22672.93 30595,22715.69 29325,22740 29375.2,22740 29425.4,22740 29475.6,22740 29525.8,22740 29576,22740 29626.2,22740 29676.4,22740 29726.6,22740 29776.8,22740 29827,22740 29877.2,22740 29927.4,22740 29977.6,22740 30027.8,22740 30078,22740 30128.2,22740 30178.4,22740 30228.6,22740 30278.8,22740 30329,22740 30379.2,22740 30429.4,22740 30479.6,22740 30529.8,22740 30580,22740 30595,22758.45 30595,22801.21 30595,22843.96 30595,22886.72 30595,22929.48 30595,22972.24 30595,23015
  other v4: 30750,19500 36200,19500 32780,21765 30750,22800 36200,22800

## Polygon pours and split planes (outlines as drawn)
CELL2IN on Top Layer "Botayer-GND" (solid, remove dead copper, pour order 1000): 33965,20980 33935,20950 33935,20235 34050,20120 34575,20120 35055,20120 35475,20540 36175,20540 36355,20720 36355,22255 36105,22505 35695,22915 35060,22915 34895,22750 34895,22305 34895,21265 34630.65,21000.65 33985.65,21000.65 33965,20980
PGND on Bottom Layer "Botayer-GND" (solid, remove dead copper, pour order 1000): 29335,19390 29320,19405 29320,22740 30590,22740 30595,22745 30595,21065 30242.94,21065 30226.47,21048.53 30210,21032.06 30210,20585 30285,20510 30595,20510 30595,19300 29340,19300 29330,19290 29320,19300 29320,19405
NetC5_1 on Bottom Layer "Botayer-GND" (solid, remove dead copper, pour order 1001): 36005,19935.2 36180,19935.2 36315,20075.59 36425,20189.98 36425,22368.6 35690,22368.6 35655,22405 35260,22405 34905,22035.83 33965,22035.83 33860,21926.64 33860,21744.65 33860,21604.26 33975,21484.67 34050,21406.68 35195,21406.68 35195,21396.28 35555,21021.91 35725,20845.13 35725,20611.15 35725,20512.35 35855,20377.16 35865,20366.76 35865,20028.79 35960,19930 36065,19930

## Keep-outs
Keep-Out Layer:
  lines w15: 29325,22730 29325,23010 ; 29325,22740 29325,19295 30595,19295 36505,19295 36505,23010 36500,23015 30595,23015 ; 29330,23015 30595,23015 ; 30590,23010 30595,23015

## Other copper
Top Layer:
  region net PGND: 30690,20615 31025,20615 31080,20560 31105,20480 31105,19935 31255,19755 31255,19740 30755,19740 30665,19830 30650,19855 30650,20395 30645,20495 30665,20585 30645,20605 30670,20630 30690,20630
  region net PGND: 32265,20310 32345,20165 32345,19720 32305,19680 31735,19675 31560,19550 31310,19550 31260,19600 31260,19710 31100,19870 31100,20310
  region net PGND: 31020,20595 31100,20410 31560,20410 31600,20465 31620,20495 31660,20545 31660,20650 31515,20730 31515,20965 31620,21010 31455,21015 31355,21015 31265,20960 31060,20815 31060,20625 31025,20615
  region net CELL2IN: 34510,20120 34510,20230 34490,20250 34385,20250 34360,20275 34360,20540 34330,20570 34000,20570 33955,20525 33955,20230 34000,20185 34180,20185 34245,20120
Bottom Layer:
  rectangle net CELL1IN: 33705,22215 34825,22935
  region net PGND: 31635,21255 31585,21200 31585,21105 31485,21105 31405,21025 31440,20940 31500,20940 31655,21100 31655,21230 31665,21246.46 31660,21255
  region net NetC5_1: 36425,22368.6 36388.6,22405 35655,22405 35655,22395 35695,22355 35708.6,22368.6
  region net OUTB: 31665,21120 31680,21105 31755,21105 31765,21115 31765,21215 31750,21230 31665,21230
  region net OUTA: 31900,21175 31925,21150 31930,21140 31930,21015 31977.35,21014.12 32015,21015 32015,21190 32005,21210 31975,21230 31900,21230
  region net NetC16_2: 31750,21090 31775,21065 31775,20945 31710,20880 31710,20760 31680,20730 31625,20730 31615,20740 31615,20870 31595,20890 31560,20890 31535,20915 31535,20955 31665,21090
  region net NetC37_2: 31320.91,22060 31400,22155 31430,22185 31465,22185 31555,22095 31555,22030 31515,21990 31350,21990 31305,22035 31320.91,22050.91
  region net CS1OUT: 31150,20190 32015,20190 32115,20290 32115,20810 32050,20875 31955,20875 31840,20795 31840,20585 31740,20450 31165,20450 31100,20370 31100,20240
  region net NetC15_2: 32070,20995 32145,21070 32805,21070 32870,21005 32870,20630 32815,20575 32640,20575 32515,20460 32485,20435 32465,20420 32400,20370 32200,20370 32145,20415 32145,20845 32100,20890 31970,20890 31940,20920 31940,20970 31965,20995
  region net +24V: 31185,19690 31225,19650 31225,19570 31275,19520 31685,19520 31780,19615 32335,19615 32370,19690 32370,20325 32480,20380 32860,20380 32945,20295 32945,20045 32890,19990 32700,19990 32650,19940 32650,19440 32530,19320 31060,19320 30970,19410 30970,19640 31020,19690
  region net PGND: 31180,21385 31180,21235 31245,21300
  region net PGND: 31350,21555 31385,21555 31450,21490 31450,21597.6 31417.6,21630
  region net PGND: 31795,21395 31880,21395 31880,21290 31862.05,21272.05 31777.05,21272.05 31777.05,21370.87
  region net NetL1_1: 35415,20490 35755,20280 35755,20070 35535,19850 34780,19850 34560,20070 34560,20250 34415,20250 34385,20280 34385,20340 34400,20355 34495,20355 34540,20400 34540,20915 34495,20955 34450,20955 34405,20960 34365,20985 34370,20990 34370,21030 34380,21040 35190,21040 35415,20815
  region net NetQ1_3: 34475,20600 34515,20640 34515,20905 34480,20940 34300,20940 34295,20935 34255,20975 34025,20975 33950,20900 33950,20640 33990,20600

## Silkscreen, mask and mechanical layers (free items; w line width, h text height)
Bottom Overlay:
  lines w10: 32190,21195 32235,21150 32235,21145
Top Solder:
  lines w15: 30690,20535 30690,20875 30735,20920 ; 30845,20105 30845,20320 31150,20625 ; 30915,20065 30915,20315 31205,20605
Bottom Solder:
  lines w15: 31965,20390 31965,20780 ; 32025,20280 32070,20325 32070,20805 ; 32025,20345 32025,20800 ; 32030,20980 32330,20980 ; 32040,20930 32325,20930
  lines w30: 34030,21655 35240,21655 35250,21645 ; 34055,21510 35205,21510 35215,21500 ; 34205,20755 34475,20755 34480,20750 ; 34225,20845 34440,20845 34445,20840 ; 34230,20665 34475,20665 ; 34500,20990 35175,20990 ; 34510,20315 35505,20315 ; 34560,20635 35395,20635 ; 34560,20845 35320,20845 ; 34570,20170 35425,20170 ; 34570,20480 35390,20480 ; 34730,19975 35520,19975 ; 34745,21805 35215,21805 35230,21820 ; 34815,21935 35210,21935 35220,21925 ; 35815,20470 35815,21390 ; 35945,20370 35945,21195 ; 36090,20375 36090,20885 ; 36220,20340 36220,21255 36230,21265 ; 36345,20240 36345,21670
